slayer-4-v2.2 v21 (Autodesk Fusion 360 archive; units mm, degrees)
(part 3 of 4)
sketch "cam-mount-standoff" plane through (0, 0, 2) normal (0, 0, 1) x axis (-1, 0, 0)
  line L1 (-27.3161, -18.7368) -> (-34.6566, -7.8543)
  line L2 (-7.8768, -19.0795) -> (-13.4582, -18.707)
  line L3 (13.4582, -18.707) -> (7.8768, -19.0795)
  line L4 (7.8768, 19.0795) -> (13.4582, 18.707)
  line L5 (-13.4582, 18.707) -> (-7.8768, 19.0795)
  line L6 (-34.6566, 7.8543) -> (-27.3161, 18.7368)
  line L7 (-34.9985, -6.7359) -> (-34.9985, 6.7359)
  line L8 (-30.1852, -9.1184) -> (-28.4467, -11.6958)
  line L9 (-25.1483, -6) -> (-28.5272, -6)
  line L10 (-28.5272, 6) -> (-25.1483, 6)
  line L11 (-28.4467, 11.6958) -> (-30.1852, 9.1184)
  line L12 (-29.9985, -3) -> (-23.1491, -3)
  line L13 (-31.9985, 1) -> (-31.9985, -1)
  line L14 (-23.1491, 3) -> (-29.9985, 3)
  line L15 (15.3479, -5.782) -> (13.4133, -8.1699)
  line L16 (19.6919, -8.9044) -> (18.7852, -6.3678)
  line L17 (13.4936, -15.6979) -> (15.3167, -15.5763)
  line L18 (13.4133, 8.1699) -> (15.3479, 5.782)
  line L19 (15.3167, 15.5763) -> (13.4936, 15.6979)
  line L20 (18.7852, 6.3678) -> (19.6919, 8.9044)
  line L21 (-15.3479, 5.782) -> (-13.4133, 8.1699)
  line L22 (-19.6919, 8.9044) -> (-18.7852, 6.3678)
  line L23 (-13.4936, 15.6979) -> (-15.3167, 15.5763)
  line L24 (-13.4133, -8.1699) -> (-15.3479, -5.782)
  line L25 (-15.3167, -15.5763) -> (-13.4936, -15.6979)
  line L26 (-18.7852, -6.3678) -> (-19.6919, -8.9044)
  line L27 (18.0216, 10.02) -> (29.5161, 10.02)
  line L28 (22.8958, 10.02) -> (20.2338, 13.9469)
  line L29 (36.0628, 10.02) -> (27.3627, 19.565)
  line L30 (40.7792, 10.02) -> (29.5161, 10.02)
  line L31 (28.5286, 16.0592) -> (34.0332, 10.02)
  line L32 (23.37, 11.9938) -> (24.708, 10.02)
  line L33 (29.4521, 15.7011) -> (38.3863, 7.4856)
  arc A1 centre (-32.9985, -6.7359) radius 2 clockwise from (-34.6566, -7.8543) to (-34.9985, -6.7359)
  arc A2 centre (-24, -16.5) radius 4 clockwise from (-22.465, -20.1938) to (-27.3161, -18.7368)
  arc A3 centre (-14.7902, -38.6626) radius 20 clockwise from (-22.465, -20.1938) to (-13.4582, -18.707)
  arc A4 centre (-9.0756, -37.0396) radius 18 clockwise from (-7.8768, -19.0795) to (-1.2965, -20.8073)
  arc A5 centre (0, -18.1019) radius 3 clockwise from (1.2965, -20.8073) to (-1.2965, -20.8073)
  arc A6 centre (9.0756, -37.0396) radius 18 clockwise from (1.2965, -20.8073) to (7.8768, -19.0795)
  arc A7 centre (14.7902, -38.6626) radius 20 clockwise from (13.4582, -18.707) to (22.465, -20.1938)
  arc A8 centre (24, -16.5) radius 4 clockwise from (26.8498, -13.6931) to (22.465, -20.1938)
  arc A9 centre (41.099, 0.3411) radius 20 clockwise from (26.8498, -13.6931) to (21.1019, 0)
  arc A10 centre (41.099, -0.3411) radius 20 clockwise from (21.1019, 0) to (26.8498, 13.6931)
  arc A11 centre (24, 16.5) radius 4 clockwise from (22.465, 20.1938) to (26.8498, 13.6931)
  arc A12 centre (14.7902, 38.6626) radius 20 clockwise from (22.465, 20.1938) to (13.4582, 18.707)
  arc A13 centre (9.0756, 37.0396) radius 18 clockwise from (7.8768, 19.0795) to (1.2965, 20.8073)
  arc A14 centre (0, 18.1019) radius 3 clockwise from (-1.2965, 20.8073) to (1.2965, 20.8073)
  arc A15 centre (-9.0756, 37.0396) radius 18 clockwise from (-1.2965, 20.8073) to (-7.8768, 19.0795)
  arc A16 centre (-14.7902, 38.6626) radius 20 clockwise from (-13.4582, 18.707) to (-22.465, 20.1938)
  arc A17 centre (-24, 16.5) radius 4 clockwise from (-27.3161, 18.7368) to (-22.465, 20.1938)
  arc A18 centre (-32.9985, 6.7359) radius 2 clockwise from (-34.9985, 6.7359) to (-34.6566, 7.8543)
  arc A19 centre (-28.5272, -8) radius 2 clockwise from (-30.1852, -9.1184) to (-28.5272, -6)
  arc A20 centre (-25.1483, -8) radius 2 clockwise from (-25.1483, -6) to (-23.376, -8.9268)
  arc A21 centre (-41.099, 0.3411) radius 20 clockwise from (-23.376, -8.9268) to (-25.1986, -11.7906)
  arc A22 centre (-26.7887, -10.5774) radius 2 clockwise from (-25.1986, -11.7906) to (-28.4467, -11.6958)
  arc A23 centre (-28.5272, 8) radius 2 clockwise from (-28.5272, 6) to (-30.1852, 9.1184)
  arc A24 centre (-26.7887, 10.5774) radius 2 clockwise from (-28.4467, 11.6958) to (-25.1986, 11.7906)
  arc A25 centre (-41.099, -0.3411) radius 20 clockwise from (-25.1986, 11.7906) to (-23.376, 8.9268)
  arc A26 centre (-25.1483, 8) radius 2 clockwise from (-23.376, 8.9268) to (-25.1483, 6)
  arc A27 centre (-41.099, -0.3411) radius 20 clockwise from (-21.1546, 1.149) to (-21.1019, 0)
  arc A28 centre (-41.099, 0.3411) radius 20 clockwise from (-21.1019, 0) to (-21.1546, -1.149)
  arc A29 centre (-23.1491, -1) radius 2 clockwise from (-21.1546, -1.149) to (-23.1491, -3)
  arc A30 centre (-29.9985, -1) radius 2 clockwise from (-29.9985, -3) to (-31.9985, -1)
  arc A31 centre (-29.9985, 1) radius 2 clockwise from (-31.9985, 1) to (-29.9985, 3)
  arc A32 centre (-23.1491, 1) radius 2 clockwise from (-23.1491, 3) to (-21.1546, 1.149)
  circle C1 centre (18.1019, 0) radius 1.05
  circle C2 centre (24, -16.5) radius 1.55
  arc A33 centre (16.9019, -7.041) radius 2 clockwise from (15.3479, -5.782) to (18.7852, -6.3678)
  arc A34 centre (14.9837, -10.5874) radius 5 clockwise from (19.6919, -8.9044) to (15.3167, -15.5763)
  arc A35 centre (13.3604, -13.7024) radius 2 clockwise from (13.4936, -15.6979) to (12.0163, -12.2214)
  arc A36 centre (10, -10) radius 3 clockwise from (12.9804, -9.6573) to (12.0163, -12.2214)
  arc A37 centre (14.9673, -9.4289) radius 2 clockwise from (12.9804, -9.6573) to (13.4133, -8.1699)
  circle C3 centre (10, -10) radius 1.05
  circle C4 centre (10, 10) radius 1.05
  arc A38 centre (14.9673, 9.4289) radius 2 clockwise from (13.4133, 8.1699) to (12.9804, 9.6573)
  arc A39 centre (10, 10) radius 3 clockwise from (12.0163, 12.2214) to (12.9804, 9.6573)
  arc A40 centre (13.3604, 13.7024) radius 2 clockwise from (12.0163, 12.2214) to (13.4936, 15.6979)
  arc A41 centre (14.9837, 10.5874) radius 5 clockwise from (15.3167, 15.5763) to (19.6919, 8.9044)
  arc A42 centre (16.9019, 7.041) radius 2 clockwise from (18.7852, 6.3678) to (15.3479, 5.782)
  circle C5 centre (24, 16.5) radius 1.55
  circle C6 centre (-24, 16.5) radius 1.55
  arc A43 centre (-16.9019, 7.041) radius 2 clockwise from (-15.3479, 5.782) to (-18.7852, 6.3678)
  arc A44 centre (-14.9837, 10.5874) radius 5 clockwise from (-19.6919, 8.9044) to (-15.3167, 15.5763)
  arc A45 centre (-13.3604, 13.7024) radius 2 clockwise from (-13.4936, 15.6979) to (-12.0163, 12.2214)
  arc A46 centre (-10, 10) radius 3 clockwise from (-12.9804, 9.6573) to (-12.0163, 12.2214)
  arc A47 centre (-14.9673, 9.4289) radius 2 clockwise from (-12.9804, 9.6573) to (-13.4133, 8.1699)
  circle C7 centre (-10, 10) radius 1.05
  circle C8 centre (-10, -10) radius 1.05
  arc A48 centre (-14.9673, -9.4289) radius 2 clockwise from (-13.4133, -8.1699) to (-12.9804, -9.6573)
  arc A49 centre (-10, -10) radius 3 clockwise from (-12.0163, -12.2214) to (-12.9804, -9.6573)
  arc A50 centre (-13.3604, -13.7024) radius 2 clockwise from (-12.0163, -12.2214) to (-13.4936, -15.6979)
  arc A51 centre (-14.9837, -10.5874) radius 5 clockwise from (-15.3167, -15.5763) to (-19.6919, -8.9044)
  arc A52 centre (-16.9019, -7.041) radius 2 clockwise from (-18.7852, -6.3678) to (-15.3479, -5.782)
  circle C9 centre (-24, -16.5) radius 1.55
  circle C10 centre (-18.1019, 0) radius 1.05
  circle C11 centre (0, -18.1019) radius 1.05
  circle C12 centre (0, 18.1019) radius 1.05
  arc A53 centre (0, 3.3668) radius 9 clockwise from (-7.5, 8.3417) to (7.5, 8.3417)
  arc A54 centre (10, 10) radius 3 clockwise from (8.3417, 7.5) to (7.5, 8.3417)
  arc A55 centre (3.3668, 0) radius 9 clockwise from (8.3417, 7.5) to (8.3417, -7.5)
  arc A56 centre (10, -10) radius 3 clockwise from (7.5, -8.3417) to (8.3417, -7.5)
  arc A57 centre (0, -3.3668) radius 9 clockwise from (7.5, -8.3417) to (-7.5, -8.3417)
  arc A58 centre (-10, -10) radius 3 clockwise from (-8.3417, -7.5) to (-7.5, -8.3417)
  arc A59 centre (-3.3668, 0) radius 9 clockwise from (-8.3417, -7.5) to (-8.3417, 7.5)
  arc A60 centre (-10, 10) radius 3 clockwise from (-7.5, 8.3417) to (-8.3417, 7.5)
  circle C13 centre (24, 16.5) radius 3.05
  circle C14 centre (24, 16.5) radius 4.55
  point P148 (22.8958, 10.02)
  point P145 (29.5161, 10.02)
  point P151 (29.5161, 10.02)
  point P150 (36.0628, 10.02)
  point P153 (34.0332, 10.02)
  point P155 (24.708, 10.02)
  point P147 (20.2338, 13.9469)
  point P156 (23.37, 11.9938)
  point P149 (27.3627, 19.565)
  point P154 (28.5286, 16.0592)
  concentric A11 C13
  coincident L27 P148
  coincident P145 P151
  parallel L27 L30
  coincident P150 L30
  coincident L30 P153
  parallel L29 L31
  parallel L28 L32
  coincident L27 P155
  concentric A11 C14
  coincident P147 C14
  tangent L28 C14
  coincident P156 C14
  coincident P149 C14
  tangent L29 C14
  coincident P154 C14
  dimension "d824" diameter C13 = 6.1 (= "( 3.05 * 2 ) * 1 mm")
  dimension "d833" distance L29 L31 = 1.5
  dimension "d834" distance L28 L32 = 1.5
  dimension "d836" distance C13 C14 = 1.5
sketch "cam-mount-skirt" plane through (0, 0, -5) normal (0, 0, 1) x axis (-1, 0, 0)
  line L1 (29.4521, 15.7011) -> (38.3863, 7.4856)
  line L2 (10.5232, 16.1251) -> (13.4179, 16.642)
  line L3 (-9.4685, 16.0316) -> (9.4685, 16.0316)
  line L4 (-13.4179, 16.642) -> (-10.5232, 16.1251)
  line L5 (-25.5, -4.935) -> (-25.5, 4.935)
  line L6 (-10.5232, -16.1251) -> (-13.4179, -16.642)
  line L7 (9.4685, -16.0316) -> (-9.4685, -16.0316)
  line L8 (13.4179, -16.642) -> (10.5232, -16.1251)
  line L9 (38.3863, -7.4856) -> (29.4521, -15.7011)
  line L10 (40.0019, 3.8052) -> (40.0019, -3.8052)
  line L11 (30.4401, -6) -> (27.7146, -6)
  line L12 (29.4762, -11.6034) -> (31.7938, -9.4722)
  line L13 (25.5, 1) -> (25.5, -1)
  line L14 (35.0019, 3) -> (27.5, 3)
  line L15 (37.0019, -1) -> (37.0019, 1)
  line L16 (27.5, -3) -> (35.0019, -3)
  line L17 (-1.1087, 6.926) -> (-3.1817, 10.8944)
  line L18 (-8.4244, 4) -> (-2.8814, 4)
  curve K1 (-10.6866, 5.436) -> (-8.4244, 4)
  curve K2 (-10.6866, 5.436) -> (-12.1729, 8.1647)
  curve K3 (-10, 11.9684) -> (-12.1729, 8.1647)
  line L19 (-4.9544, 11.9684) -> (-10, 11.9684)
  line L20 (10, 11.9684) -> (2.9431, 11.9684)
  curve K4 (10, 11.9684) -> (12.1729, 8.1647)
  curve K5 (10.6866, 5.436) -> (12.1729, 8.1647)
  curve K6 (10.6866, 5.436) -> (8.4244, 4)
  line L21 (5.0161, 4) -> (8.4244, 4)
  line L22 (1.1704, 9.0423) -> (3.2434, 5.074)
  line L23 (2.9431, -11.9684) -> (10, -11.9684)
  line L24 (3.2434, -5.074) -> (1.1704, -9.0423)
  line L25 (8.4244, -4) -> (5.0161, -4)
  curve K7 (10.6866, -5.436) -> (8.4244, -4)
  curve K8 (10.6866, -5.436) -> (12.1729, -8.1647)
  curve K9 (10, -11.9684) -> (12.1729, -8.1647)
  line L26 (-3.1817, -10.8944) -> (-1.1087, -6.926)
  line L27 (-10, -11.9684) -> (-4.9544, -11.9684)
  curve K10 (-10, -11.9684) -> (-12.1729, -8.1647)
  curve K11 (-10.6866, -5.436) -> (-12.1729, -8.1647)
  curve K12 (-10.6866, -5.436) -> (-8.4244, -4)
  line L28 (-2.8814, -4) -> (-8.4244, -4)
  curve K13 (15, 0) -> (18.1183, 6.0086)
  curve K14 (18.1183, 6.0086) -> (22.5, 4.3626)
  line L29 (22.5, -4.3626) -> (22.5, 4.3626)
  curve K15 (18.1183, -6.0086) -> (22.5, -4.3626)
  curve K16 (15, 0) -> (18.1183, -6.0086)
  line L30 (-22.5, 4.3626) -> (-22.5, -4.3626)
  curve K17 (-18.1183, 6.0086) -> (-22.5, 4.3626)
  curve K18 (-15, 0) -> (-18.1183, 6.0086)
  curve K19 (-15, 0) -> (-18.1183, -6.0086)
  curve K20 (-18.1183, -6.0086) -> (-22.5, -4.3626)
  line L31 (27.7146, 6) -> (30.4401, 6)
  line L32 (31.7938, 9.4722) -> (29.4762, 11.6034)
  line L33 (35.8754, 11.8323) -> (41.5019, 6.6585)
  line L34 (41.5019, 6.6585) -> (41.5019, 0)
  line L35 (34.8601, 10.7281) -> (35.8754, 11.8323)
  line L36 (40.0019, 0) -> (41.5019, 0)
  arc A1 centre (35.0019, 3.8052) radius 5 clockwise from (38.3863, 7.4856) to (40.0019, 3.8052)
  arc A2 centre (34.8671, 21.5899) radius 8 clockwise from (29.4521, 15.7011) to (27.6224, 18.1966)
  arc A3 centre (24, 16.5) radius 4 clockwise from (21.8856, 19.8955) to (27.6224, 18.1966)
  arc A4 centre (9.199, 40.2682) radius 24 clockwise from (21.8856, 19.8955) to (13.4179, 16.642)
  arc A5 centre (9.4685, 22.0316) radius 6 clockwise from (10.5232, 16.1251) to (9.4685, 16.0316)
  arc A6 centre (-9.4685, 22.0316) radius 6 clockwise from (-9.4685, 16.0316) to (-10.5232, 16.1251)
  arc A7 centre (-9.199, 40.2682) radius 24 clockwise from (-13.4179, 16.642) to (-21.8856, 19.8955)
  arc A8 centre (-24, 16.5) radius 4 clockwise from (-27.6429, 14.8479) to (-21.8856, 19.8955)
  arc A9 centre (-49.5, 4.935) radius 24 clockwise from (-27.6429, 14.8479) to (-25.5, 4.935)
  arc A10 centre (-49.5, -4.935) radius 24 clockwise from (-25.5, -4.935) to (-27.6429, -14.8479)
  arc A11 centre (-24, -16.5) radius 4 clockwise from (-21.8856, -19.8955) to (-27.6429, -14.8479)
  arc A12 centre (-9.199, -40.2682) radius 24 clockwise from (-21.8856, -19.8955) to (-13.4179, -16.642)
  arc A13 centre (-9.4685, -22.0316) radius 6 clockwise from (-10.5232, -16.1251) to (-9.4685, -16.0316)
  arc A14 centre (9.4685, -22.0316) radius 6 clockwise from (9.4685, -16.0316) to (10.5232, -16.1251)
  arc A15 centre (9.199, -40.2682) radius 24 clockwise from (13.4179, -16.642) to (21.8856, -19.8955)
  arc A16 centre (24, -16.5) radius 4 clockwise from (27.6224, -18.1966) to (21.8856, -19.8955)
  arc A17 centre (34.8671, -21.5899) radius 8 clockwise from (27.6224, -18.1966) to (29.4521, -15.7011)
  arc A18 centre (35.0019, -3.8052) radius 5 clockwise from (40.0019, -3.8052) to (38.3863, -7.4856)
  arc A19 centre (49.5, -4.935) radius 24 clockwise from (26.179, -10.6035) to (25.7341, -8.2786)
  arc A20 centre (27.7146, -8) radius 2 clockwise from (25.7341, -8.2786) to (27.7146, -6)
  arc A21 centre (30.4401, -8) radius 2 clockwise from (30.4401, -6) to (31.7938, -9.4722)
  arc A22 centre (28.1225, -10.1312) radius 2 clockwise from (29.4762, -11.6034) to (26.179, -10.6035)
  arc A23 centre (27.5, 1) radius 2 clockwise from (25.5, 1) to (27.5, 3)
  arc A24 centre (35.0019, 1) radius 2 clockwise from (35.0019, 3) to (37.0019, 1)
  arc A25 centre (35.0019, -1) radius 2 clockwise from (37.0019, -1) to (35.0019, -3)
  arc A26 centre (27.5, -1) radius 2 clockwise from (27.5, -3) to (25.5, -1)
  circle C1 centre (24, 16.5) radius 1.55
  circle C2 centre (-24, 16.5) radius 1.55
  arc A27 centre (-2.8814, 6) radius 2 clockwise from (-1.1087, 6.926) to (-2.8814, 4)
  arc A28 centre (-4.9544, 9.9684) radius 2 clockwise from (-4.9544, 11.9684) to (-3.1817, 10.8944)
  arc A29 centre (5.0161, 6) radius 2 clockwise from (5.0161, 4) to (3.2434, 5.074)
  arc A30 centre (2.9431, 9.9684) radius 2 clockwise from (1.1704, 9.0423) to (2.9431, 11.9684)
  arc A31 centre (2.9431, -9.9684) radius 2 clockwise from (2.9431, -11.9684) to (1.1704, -9.0423)
  arc A32 centre (5.0161, -6) radius 2 clockwise from (3.2434, -5.074) to (5.0161, -4)
  arc A33 centre (-4.9544, -9.9684) radius 2 clockwise from (-3.1817, -10.8944) to (-4.9544, -11.9684)
  arc A34 centre (-2.8814, -6) radius 2 clockwise from (-2.8814, -4) to (-1.1087, -6.926)
  circle C3 centre (-24, -16.5) radius 1.55
  circle C4 centre (24, -16.5) radius 1.55
  arc A35 centre (30.4401, 8) radius 2 clockwise from (31.7938, 9.4722) to (30.4401, 6)
  arc A36 centre (27.7146, 8) radius 2 clockwise from (27.7146, 6) to (25.7341, 8.2786)
  arc A37 centre (49.5, 4.935) radius 24 clockwise from (25.7341, 8.2786) to (26.179, 10.6035)
  arc A38 centre (28.1225, 10.1312) radius 2 clockwise from (26.179, 10.6035) to (29.4762, 11.6034)
  point P132 (41.5019, 6.6585)
  point P133 (41.5019, 6.6585)
  point P134 (34.8601, 10.7281)
  point P135 (40.0019, 0)
  coincident P132 P133
  coincident L1 P134
  perpendicular L1 L35
  midpoint L10 P135
  perpendicular L10 L36
  dimension "d828" distance L1 L33 = 1.5
  dimension "d829" distance L10 L34 = 1.5
extrude "Extrude2" new body sketch "cam-mount-standoff" profile of A10 A11 A12 C13 L27 L28 L29 L30 L31 L32 C14 along normal blind 26.3
base_feature "Base Feature1" bodies "top (1)"
move "Move2"
move "Move1"
work_plane "WorkPlane1" AlongDistance 7
work_plane "WorkPlane2" AlongDistance -22.896 (= "-23.00 mm + 0.104 mm")
extrude "Extrude3" add of existing geometry blind 16
split "Split1" bodies "cam-mount-shell (1)"
split "Split2" bodies "cam-mount-shell (2)"
position "Position10"
sketch "Sketch3" plane through (0, 0, 7) normal (0, 0, -1) x axis (1, 0, 0)
  line L1 (-41.2228, 11.52) -> (-22.896, 11.52)
  line L2 (-41.2228, 0) -> (-41.2228, 11.52)
  line L3 (-38.6076, 0) -> (-41.2228, 0)
  line L4 (-38.6076, 10.02) -> (-38.6076, 0)
  line L5 (-22.896, 10.02) -> (-38.6076, 10.02)
  line L6 (-22.896, 11.52) -> (-22.896, 10.02)
  line L7 (-39.7228, 10.02) -> (-38.6076, 10.02)
  line L8 (-39.7228, 0) -> (-39.7228, 10.02)
  point P6 (-38.6076, 10.02)
  point P8 (-38.6076, 10.02)
  point P10 (-39.7228, 0)
  coincident P6 P8
  perpendicular L4 L7
  coincident L3 P10
  perpendicular L3 L8
  dimension "d841" distance L2 L8 = 1.5
extrude "Extrude4" cut sketch "Sketch3" profile of L3 L4 L7 L8 against normal blind 2.5
extrude "Extrude5" add of existing geometry blind 5
chamfer "Chamfer1" distance 2
sketch "Sketch4" plane through (0, 0, 28.3) normal (0, 0, 1) x axis (-1, 0, 0)
  line L1 (34.2399, 12.02) -> (32.2103, 12.02)
  line L2 (27.3627, 19.565) -> (34.2399, 12.02)
  line L3 (22.8958, 10.02) -> (20.2338, 13.9469)
  line L4 (24.708, 10.02) -> (22.8958, 10.02)
  line L5 (23.37, 11.9938) -> (24.708, 10.02)
  line L6 (32.2103, 12.02) -> (28.5286, 16.0592)
  line L7 (21.4754, 14.7886) -> (23.37, 11.9938)
  line L8 (26.2541, 18.5546) -> (28.5286, 16.0592)
  line L9 (20.2338, 13.9469) -> (21.4754, 14.7886)
  arc A1 centre (24, 16.5) radius 4.55 clockwise from (20.2338, 13.9469) to (27.3627, 19.565)
  arc A2 centre (24, 16.5) radius 4.55 clockwise from (28.5286, 16.0592) to (23.37, 11.9938)
  circle C1 centre (24, 16.5) radius 3.05
  point P9 (23.37, 11.9938)
  point P11 (23.37, 11.9938)
  point P12 (21.4754, 14.7886)
  point P10 (28.5286, 16.0592)
  point P13 (28.5286, 16.0592)
  point P14 (26.2541, 18.5546)
  point P5 (20.2338, 13.9469)
  point P15 (20.2338, 13.9469)
  coincident P9 P11
  coincident C1 P12
  tangent C1 L7
  coincident P10 P13
  coincident C1 P14
  tangent C1 L8
  coincident P5 P15
extrude "Extrude6" cut sketch "Sketch4" profile of A2 C1 L7 L8 against normal blind 46
extrude "Extrude7" cut sketch "Sketch4" profile of L3 L4 L5 L7 L9 against normal blind 6
sketch "Sketch5" plane through (0, 0, 2) normal (0, 0, -1) x axis (1, 0, 0)
  line L1 (-22.896, 10.02) -> (-39.7228, 10.02)
  line L2 (-22.896, 11.52) -> (-22.896, 10.02)
  line L3 (-41.2228, 11.52) -> (-22.896, 11.52)
  line L4 (-41.2228, 0) -> (-41.2228, 11.52)
  line L5 (-39.7228, 0) -> (-41.2228, 0)
  line L6 (-39.7228, 10.02) -> (-39.7228, 0)
  line L7 (-34.8601, 10.7281) -> (-35.8754, 11.8323)
  line L8 (-34.209, 10.02) -> (-34.8601, 10.7281)
  line L9 (-36.2248, 12.2122) -> (-35.8754, 11.8323)
  point P9 (-34.8601, 10.7281)
  point P10 (-34.8601, 10.7281)
  point P11 (-34.209, 10.02)
  point P8 (-35.8754, 11.8323)
  point P12 (-35.8754, 11.8323)
  coincident P9 P10
  coincident L1 P11
  parallel L7 L8
  coincident P8 P12
  parallel L7 L9
extrude "Extrude8" cut sketch "Sketch5" profile of L1 L3 L4 L5 L6 L7 L8 L9 against normal blind 5
combine "Combine1" bodies "cam-mount-shell (2)"
loft "Loft1" sketch "cam-mount-skirt"
fillet "Fillet1" radius 3
fillet "Fillet2" radius 2
fillet "Fillet3" radius 1
fillet "Fillet4" radius 2
fillet "Fillet5" radius 2
fillet "Fillet6" radius 1
fillet "Fillet7" radius 2
chamfer "Chamfer2" distance 1
chamfer "Chamfer3" distance 2
chamfer "Chamfer4" distance 1
component_insert "Component Insert2"
sketch "Sketch7" plane through (0, -10.02, 0) normal (0, 1, 0) x axis (-1, 0, 0)
  curve K1 (33.4338, 2) -> (34.0973, 7)
  line L1 (34.0973, 7) -> (34.209, 7)
  line L2 (35.4854, 7) -> (34.209, 7)
  line L3 (39.7228, 7.7809) -> (39.7228, 7)
  line L4 (43.1065, 10.1501) -> (39.7228, 7.7809)
  line L5 (36.0628, 20.2095) -> (43.1065, 10.1501)
  line L6 (34.0332, 23.1081) -> (36.0628, 20.2095)
  line L7 (22.896, 20.4629) -> (31.612, 26.566)
  line L8 (22.896, 22.2941) -> (22.896, 20.4629)
  line L9 (22.9044, 22.3) -> (22.896, 22.2941)
  line L10 (22.8958, 22.3) -> (22.9044, 22.3)
  line L11 (22.8958, 2) -> (22.8958, 22.3)
  line L12 (33.4338, 2) -> (22.8958, 2)
  curve K2 (33.26, 14.3566) -> (32.1953, 15.8771)
  line L13 (39.7228, 7) -> (35.4854, 7)
  line L14 (31.612, 26.566) -> (34.0332, 23.1081)
  arc A1 centre (32.9724, 15.2882) radius 0.975 clockwise from (33.26, 14.3566) to (32.1953, 15.8771)
extrude "Extrude9" cut sketch "Sketch7" profile of K2 A1 against normal blind 10.5
sketch "Sketch8" plane through (0, -11.52, 0) normal (0, -1, 0) x axis (1, 0, 0)
  curve K1 (-35.5375, 7) -> (-34.9976, 2)
  line L1 (-34.6956, 2) -> (-34.9976, 2)
  line L2 (-34.6956, 22.6295) -> (-34.6956, 2)
  curve K2 (-34.6956, 22.6295) -> (-44.2989, 9.154)
  line L3 (-41.2228, 7) -> (-44.2989, 9.154)
  line L4 (-35.5375, 7) -> (-35.5883, 7)
  curve K3 (-32.1953, 15.8771) -> (-33.26, 14.3566)
  line L5 (-36.1672, 7) -> (-41.2228, 7)
  line L6 (-35.5883, 7) -> (-36.1672, 7)
  arc A1 centre (-32.9724, 15.2882) radius 0.975 clockwise from (-32.1953, 15.8771) to (-33.26, 14.3566)
  circle C1 centre (-32.9724, 15.2882) radius 2.65
  concentric A1 C1
  dimension "d874" diameter C1 = 5.3
extrude "Extrude10" cut sketch "Sketch8" profile of L2 A1 K3 C1 along normal blind 8.5
fillet "Fillet8" radius 3
extrude "Extrude11" add of existing geometry blind 2
fillet "Fillet9" radius 5
mirror "Mirror1" mirrorStitchTolerance 0.1
position "Position9"
position "Position8"
position "Position6"
position "Position7"
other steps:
base_feature "Base Feature1" bodies "cam-mount-shell"
base_feature "Base Feature4"
base_feature "Base Feature3"
base_feature "Base Feature2"
joint_origin "JointOrigin4"
create_component "CreateComponent2"
remove_instance "RemoveInstance2"
remove_instance "RemoveInstance3"
remove_instance "RemoveInstance4"
remove_instance "RemoveInstance5"
remove_instance "RemoveInstance6"
remove_instance "RemoveInstance7"
remove_instance "RemoveInstance8"
remove_instance "RemoveInstance9"
remove_instance "RemoveInstance10"
remove_instance "RemoveInstance11"
remove_instance "RemoveInstance12"
remove_instance "RemoveInstance13"
remove_instance "RemoveInstance14"
joint_origin "JointOrigin5"
joint_origin "JointOrigin6"
joint_origin "JointOrigin7"
joint_origin "JointOrigin8"
joint_origin "JointOrigin9"
joint_origin "JointOrigin10"
create_component "CreateComponent3"
remove_instance "RemoveInstance16"
create_component "CreateComponent1"
named bodies: "center-upper", "arm-fl", "arm-rr", "arm-rl", "center-lower", "cam-mount-shell", "canopy", "cam-mount-shell (1)", "canopy (1)", "canopy-v2", "cam-mount-35", "top (1)", "cam-mount-shell (2)", "puzzle", "arm-fr"

design "20x20 Flight Controller"
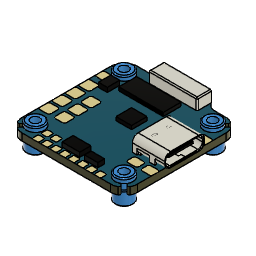
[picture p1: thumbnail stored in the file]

design "Slayer Hurricane 4040"
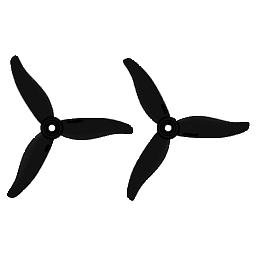
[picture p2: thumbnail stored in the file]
sketch "Sketch1" plane through (0, 0, 0) normal (0, 1, 0) x axis (1, 0, 0)
  curve K1 (5.4694, -4.0404) -> (5.1621, 4.4263)
  curve K2 (23.4739, 6.387) -> (7.3147, 5.303)
  curve K3 (43.581, 4.1632) -> (31.5201, 5.982)
  curve K4 (18.3421, -7.4304) -> (33.5067, -4.4448)
  curve K5 (4.6655, -5.2742) -> (19.2218, -7.6881)
  curve K6 (39.69, -3.7559) -> (54.3074, -3.2468)
  curve K7 (53.947, -7.3026) -> (46.4681, 7.5356)
  curve K8 (51.5, 0) -> (44.2123, 4.0129)
  line L1 (78.7648, 0) -> (0, 0)
  curve K9 (47.845, -5.7624) -> (53.4117, -0.1713)
  curve K10 (8.9395, 5.261) -> (1.3848, 3.5917)
  circle C1 centre (0, 0) radius 6.8
  circle C2 centre (0, 0) radius 2.5
  circle C3 centre (0, 0) radius 50.8
  point P1 (0, 0)
  point P2 (0, 0)
  point P3 (0, 0)
  point P4 (5.1621, 4.4263)
  point P14 (5.4694, -4.0404)
  point P5 (15.3943, 5.845)
  point P6 (37.5505, 5.0726)
  point P12 (25.9244, -5.9376)
  point P13 (11.9437, -6.4811)
  point P10 (46.9987, -3.5013)
  point P8 (50.2076, 0.1165)
  point P7 (47.8561, 2.0065)
  point P29 (0, 0)
  point P9 (50.6284, -2.9668)
  coincident P1 P2
  coincident P1 P3
  coincident C1 P4
  coincident C1 P14
  midpoint P5 K2
  midpoint P6 K3
  midpoint P12 K4
  midpoint P13 K5
  midpoint P10 K6
  midpoint P8 K7
  midpoint P7 K8
  coincident P1 P29
  midpoint P9 K9
  midpoint P4 K10
  concentric C2 C3
  dimension "d1" diameter C1 = 13.6
  dimension "d2" diameter C2 = 5
  dimension "d78" diameter C3 = 101.6 (= "4")
extrude "Extrude1" new body sketch "Sketch1" profile of C1 C2 distance 7
work_plane "WorkPlane6" AlongDistance 4.5
sketch "Sketch3" plane through (4.5, 0, 0) normal (1, 0, 0) x axis (0, 0, -1)
  line L1 (6.8, -3.5) -> (-6.8, -3.5)
  line L2 (-6.8, 3.5) -> (6.8, 3.5)
  line L3 (4, -3.5) -> (4, 3.5)
  line L4 (-3.75, -3.5) -> (-3.75, 3.5)
  curve K1 (-3.75, -3.1239) -> (-3.75, -3.1239)
  curve K2 (-3.5611, -3.317) -> (-3.9389, -2.9308)
  curve K3 (0.2448, -0.7564) -> (-2.2448, -2.2436)
  curve K4 (-3.5886, -0.8664) -> (-0.9748, 1.9804)
  curve K5 (3.4341, 3.3087) -> (4.5659, 2.0069)
  curve K6 (0.0208, 2.5606) -> (2.6178, 3.2817)
  point P7 (4, 3.5)
  point P9 (-3.75, 3.5)
  point P11 (-3.75, -3.1239)
  point P14 (4, 2.6578)
  point P12 (-1, -1.5)
  point P16 (-2.2817, 0.557)
  point P15 (1.3193, 2.9212)
  point P1 (0, 0)
  vertical L3
  coincident L2 P7
  vertical L4
  coincident L2 P9
  coincident L4 P11
  coincident L3 P14
  midpoint P11 K2
  midpoint P12 K3
  midpoint P16 K4
  midpoint P14 K5
  midpoint P15 K6
  dimension "d15" distance P1 L3 = 4
  dimension "d17" distance P1 L4 = 3.75
work_plane "WorkPlane4" AlongDistance 22
sketch "Sketch5" plane through (22, 0, 0) normal (1, 0, 0) x axis (0, 0, -1)
  line L1 (6.0622, 0) -> (-7.0278, 0)
  curve K1 (-4.0404, 0) -> (4.4263, 0)
  line L2 (-7.0278, -3) -> (-7.0278, 0)
  line L3 (6.0622, 3.7) -> (6.0622, 0)
  curve K2 (-7.0278, -3) -> (-7.0278, -3)
  curve K3 (-6.9778, -3.0682) -> (-7.0777, -2.9318)
  point P4 (0, 0)
  point P2 (-7.0278, 0)
  point P7 (-7.0278, -3)
  horizontal L1
  coincident L1 P4
  coincident P2 K1
  perpendicular L1 L2
  midpoint P7 K3
sketch "Sketch8" plane through (22, 0, 0) normal (1, 0, 0) x axis (0, 0, -1)
  curve K1 (-2.9668, 0) -> (-3.75, -3.1239)
  curve K2 (-2.8869, -0.0865) -> (-3.9842, -1.0525)
  curve K3 (0.1695, 0.6998) -> (-6.1031, -0.6998)
  curve K4 (-2.9668, 0) -> (4, 2.6578)
  curve K5 (-7.413, -2.6683) -> (-5.5637, -3.3317)
  curve K6 (5.0928, 3.4589) -> (2.9072, 1.8566)
  point P2 (-3.75, -3.1239)
  point P5 (-3.75, -3.1239)
  point P4 (-2.9668, 0)
  point P7 (-2.9668, 0)
  point P10 (-3.4355, -0.5695)
  point P9 (4, 2.6578)
  point P15 (4, 2.6578)
  point P3 (-6.4884, -3)
  point P8 (6.0622, 3.7)
  point P16 (6.0622, 3.7)
  point P6 (-7.0278, -3)
  point P11 (-7.0278, -3)
  coincident P2 P5
  coincident P4 P7
  midpoint P10 K2
  midpoint P4 K3
  coincident P9 P15
  midpoint P3 K5
  midpoint P15 K6
  coincident P8 P16
  coincident P6 P11
loft "Loft1" sketch "Sketch3" + "Sketch5"
sketch "Sketch20" plane through (0, 0, 0) normal (0, 0, 1) x axis (1, 0, 0)
  curve K1 (50.6284, 0) -> (4.5, 2.6578)
  curve K2 (50.6284, 0) -> (4.5, -3.1239)
  line L1 (4.5, -3.1239) -> (4.5, 2.6578)
  curve K3 (50.6534, 0.1104) -> (4.5, 2.6578)
  curve K4 (22.5489, 5.3352) -> (5.6822, 3.6687)
  curve K5 (5.6102, 3.6045) -> (3.3898, 1.711)
  curve K6 (32.3804, 4.5964) -> (22.8999, 4.8276)
  curve K7 (42.9585, 3.0539) -> (29.1858, 4.862)
  curve K8 (51.8068, -1.7792) -> (49.5, 2)
  line L2 (6.8, -3.5) -> (-6.8, -3.5)
  line L3 (-6.8, 3.5) -> (6.8, 3.5)
  line L4 (6.8, 3.4201) -> (6.8, 3.5)
  line L5 (6.8, -3.5) -> (6.8, -3.2275)
  line L6 (0, 3.5) -> (0, -3.5)
  line L7 (6.8, -3.5) -> (0, -3.5)
  line L8 (0, 3.5) -> (6.8, 3.5)
  point P2 (4.5, 2.6578)
  point P6 (4.5, 2.6578)
  point P4 (4.5, -3.1239)
  point P7 (4.5, -3.1239)
  point P8 (4.5, 2.6578)
  point P12 (50.6534, 0.1104)
  point P9 (14.1155, 4.5019)
  point P10 (27.6402, 4.712)
  point P11 (36.0721, 3.958)
  point P25 (6.8, 3.5)
  point P27 (6.8, 3.5)
  point P28 (6.8, 3.4201)
  point P29 (6.8, -3.2275)
  point P24 (6.8, -3.5)
  point P30 (6.8, -3.5)
  point P1 (0, 0)
  point P31 (0, -3.5)
  point P33 (6.8, 3.5)
  coincident P2 P6
  coincident P4 P7
  coincident P6 P8
  coincident K1 P12
  midpoint P9 K4
  midpoint P8 K5
  midpoint P10 K6
  midpoint P11 K7
  midpoint P12 K8
  coincident P25 P27
  coincident K3 P28
  perpendicular L3 L4
  coincident K2 P29
  coincident P24 P30
  perpendicular L2 L5
  perpendicular L2 L6
  midpoint P1 L6
  midpoint L2 P31
  coincident P25 P33
circular_pattern "C-Pattern1" TotalAngle 360
combine "Combine1"
fillet "Fillet1" radius 0.15 0.2 0.2
chamfer "Chamfer1" distance 1
sketch "Sketch9" plane through (0, 3.5, 0) normal (0, 1, 0) x axis (-1, 0, 0)
  line L1 (2.4871, -1.6776) -> (0, 0)
  line L2 (2.3103, -0.9552) -> (1.7511, -1.7843)
  line L3 (3, 0) -> (0, 0)
  curve K1 (4.241, -5.0571) -> (6.0041, -2.7407)
  curve K2 (2.2591, 6.2013) -> (-0.6285, 6.57)
  curve K3 (-6.5001, -1.1442) -> (-5.3755, -3.8293)
  circle C1 centre (0, 0) radius 2.5
  circle C2 centre (0, 0) radius 4.75
  circle C3 centre (0, 0) radius 2.5
  circle C4 centre (0, 0) radius 3
  arc A1 centre (2.0707, -1.3967) radius 0.5023 clockwise from (2.3103, -0.9552) to (1.7511, -1.7843)
  arc A2 centre (0, 0) radius 6.6 clockwise from (4.241, -5.0571) to (-5.3755, -3.8293)
  arc A3 centre (0, 0) radius 6.6 clockwise from (2.2591, 6.2013) to (6.0041, -2.7407)
  arc A4 centre (0, 0) radius 6.6 clockwise from (-6.5001, -1.1442) to (-0.6285, 6.57)
  point P1 (0, 0)
  point P3 (0, 0)
  point P4 (0, 0)
  point P6 (0, 0)
  point P7 (2.4871, -1.6776)
  point P9 (2.3103, -0.9552)
  point P8 (1.7511, -1.7843)
  point P11 (2.0307, -1.3697)
  point P12 (0, 0)
  point P13 (3, 0)
  coincident P1 P3
  concentric C3 C4
  coincident P4 P6
  coincident C4 P7
  coincident P7 A1
  tangent C4 A1
  coincident C1 P9
  coincident C1 P8
  coincident L1 P11
  perpendicular L1 L2
  midpoint P11 L2
  coincident P1 P12
  coincident C4 P13
  horizontal L3
  dimension "d24" diameter C2 = 9.5
  dimension "d25" diameter C4 = 6
  dimension "d26" distance P8 P9 = 1
  dimension "d35" angle L1 L3 = 34
move "Move1" TranslateX 0 TranslateY -0.025 TranslateZ 0
extrude "Extrude2" add sketch "Sketch9" profile of C1 C2 C3 C4 L1 A1 to an object
chamfer "Chamfer2" distance 0.5
extrude "Extrude3" cut sketch "Sketch9" profile of C1 C3 A1 L2 against normal blind 2
circular_pattern "C-Pattern2" TotalAngle 360
fillet "Fillet2" radius 0.1
fillet "Fillet3" radius 0.1
work_plane "WorkPlane7" AlongDistance 8
sketch "Gemfan Logo" plane through (0, 0, 0) normal (0, 1, 0) x axis (1, 0, 0)
  line L1 (-26.4232, -3.0069) -> (-28.2247, -3.1174)
  curve K1 (-26.4124, -3.6617) -> (-26.4232, -3.0069)
  curve K2 (-25.7177, -4.026) -> (-26.4124, -3.6617)
  curve K3 (-25.0425, -3.8398) -> (-25.7177, -4.026)
  curve K4 (-24.6809, -3.408) -> (-25.0425, -3.8398)
  curve K5 (-24.7437, -2.9905) -> (-24.6809, -3.408)
  curve K6 (-25.5749, -2.6426) -> (-24.7437, -2.9905)
  curve K7 (-27.0668, -1.9141) -> (-25.5749, -2.6426)
  curve K8 (-27.197, -0.7559) -> (-27.0668, -1.9141)
  curve K9 (-26.632, 0.1179) -> (-27.197, -0.7559)
  curve K10 (-25.606, 0.7646) -> (-26.632, 0.1179)
  curve K11 (-24.0506, 0.9999) -> (-25.606, 0.7646)
  curve K12 (-22.4421, 0.5722) -> (-24.0506, 0.9999)
  curve K13 (-22.1863, -0.7886) -> (-22.4421, 0.5722)
  line L2 (-23.9687, -0.8909) -> (-22.1863, -0.7886)
  curve K14 (-24.0611, -0.3016) -> (-23.9687, -0.8909)
  curve K15 (-24.6144, -0.1174) -> (-24.0611, -0.3016)
  curve K16 (-25.1481, -0.2545) -> (-24.6144, -0.1174)
  curve K17 (-25.4252, -0.5881) -> (-25.1481, -0.2545)
  curve K18 (-25.3777, -0.8459) -> (-25.4252, -0.5881)
  curve K19 (-24.8307, -1.0669) -> (-25.3777, -0.8459)
  curve K20 (-23.2694, -1.5969) -> (-24.8307, -1.0669)
  curve K21 (-22.73, -2.262) -> (-23.2694, -1.5969)
  curve K22 (-22.7924, -3.1502) -> (-22.73, -2.262)
  curve K23 (-23.4733, -4.2143) -> (-22.7924, -3.1502)
  curve K24 (-24.6166, -4.953) -> (-23.4733, -4.2143)
  curve K25 (-26.1469, -5.2047) -> (-24.6166, -4.953)
  curve K26 (-28.0667, -4.6154) -> (-26.1469, -5.2047)
  curve K27 (-28.2247, -3.1174) -> (-28.0667, -4.6154)
  line L3 (-18.6296, 0.8976) -> (-20.4837, 0.8976)
  line L4 (-20.1666, -3.6249) -> (-18.6296, 0.8976)
  line L5 (-17.273, -3.6249) -> (-20.1666, -3.6249)
  line L6 (-17.7751, -5.1024) -> (-17.273, -3.6249)
  line L7 (-22.5227, -5.1024) -> (-17.7751, -5.1024)
  line L8 (-20.4837, 0.8976) -> (-22.5227, -5.1024)
  line L9 (-15.0116, -4.112) -> (-12.9067, -4.112)
  line L10 (-15.6406, -5.1024) -> (-15.0116, -4.112)
  line L11 (-17.5337, -5.1024) -> (-15.6406, -5.1024)
  line L12 (-13.2395, 0.8976) -> (-17.5337, -5.1024)
  line L13 (-11.2171, 0.8976) -> (-13.2395, 0.8976)
  line L14 (-11.0016, -5.1024) -> (-11.2171, 0.8976)
  line L15 (-12.9431, -5.1024) -> (-11.0016, -5.1024)
  line L16 (-12.9067, -4.112) -> (-12.9431, -5.1024)
  line L17 (-12.7796, -0.6577) -> (-12.8504, -2.8145)
  line L18 (-14.168, -2.8145) -> (-12.7796, -0.6577)
  line L19 (-12.8504, -2.8145) -> (-14.168, -2.8145)
  line L20 (-7.6316, 0.8976) -> (-9.691, 0.8976)
  line L21 (-7.1107, -1.1265) -> (-7.6316, 0.8976)
  line L22 (-5.2114, 0.8976) -> (-7.1107, -1.1265)
  line L23 (-3.1631, 0.8976) -> (-5.2114, 0.8976)
  line L24 (-6.681, -2.5894) -> (-3.1631, 0.8976)
  line L25 (-7.535, -5.1024) -> (-6.681, -2.5894)
  line L26 (-9.3931, -5.1024) -> (-7.535, -5.1024)
  line L27 (-8.5391, -2.5894) -> (-9.3931, -5.1024)
  line L28 (-9.691, 0.8976) -> (-8.5391, -2.5894)
  line L29 (2.399, 0.8976) -> (-2.5696, 0.8976)
  line L30 (1.9637, -0.3834) -> (2.399, 0.8976)
  line L31 (-1.1469, -0.3834) -> (1.9637, -0.3834)
  line L32 (-1.4709, -1.3371) -> (-1.1469, -0.3834)
  line L33 (1.4145, -1.3371) -> (-1.4709, -1.3371)
  line L34 (0.9986, -2.5608) -> (1.4145, -1.3371)
  line L35 (-1.8868, -2.5608) -> (0.9986, -2.5608)
  line L36 (-2.2888, -3.7436) -> (-1.8868, -2.5608)
  line L37 (0.9117, -3.7436) -> (-2.2888, -3.7436)
  line L38 (0.45, -5.1024) -> (0.9117, -3.7436)
  line L39 (-4.6087, -5.1024) -> (0.45, -5.1024)
  line L40 (-2.5696, 0.8976) -> (-4.6087, -5.1024)
  line L41 (3.5123, 0.8976) -> (1.4732, -5.1024)
  line L42 (6.6023, 0.8976) -> (3.5123, 0.8976)
  curve K28 (7.866, 0.7503) -> (6.6023, 0.8976)
  curve K29 (8.4129, 0.2039) -> (7.866, 0.7503)
  curve K30 (8.3608, -0.7682) -> (8.4129, 0.2039)
  curve K31 (7.8551, -1.6297) -> (8.3608, -0.7682)
  curve K32 (7.07, -2.217) -> (7.8551, -1.6297)
  curve K33 (6.3381, -2.4544) -> (7.07, -2.217)
  curve K34 (6.7456, -2.6756) -> (6.3381, -2.4544)
  curve K35 (6.9349, -2.991) -> (6.7456, -2.6756)
  curve K36 (7.0679, -3.3638) -> (6.9349, -2.991)
  line L43 (7.3749, -5.1024) -> (7.0679, -3.3638)
  line L44 (5.28, -5.1024) -> (7.3749, -5.1024)
  line L45 (4.9121, -3.2688) -> (5.28, -5.1024)
  curve K37 (4.7337, -2.8064) -> (4.9121, -3.2688)
  curve K38 (4.3267, -2.6672) -> (4.7337, -2.8064)
  line L46 (4.1629, -2.6672) -> (4.3267, -2.6672)
  line L47 (3.3354, -5.1024) -> (4.1629, -2.6672)
  line L48 (1.4732, -5.1024) -> (3.3354, -5.1024)
  line L49 (5.33, -1.5335) -> (4.5482, -1.5335)
  curve K39 (5.8489, -1.4517) -> (5.33, -1.5335)
  curve K40 (6.2137, -1.2634) -> (5.8489, -1.4517)
  curve K41 (6.4486, -0.9155) -> (6.2137, -1.2634)
  curve K42 (6.416, -0.4694) -> (6.4486, -0.9155)
  curve K43 (5.7772, -0.3139) -> (6.416, -0.4694)
  line L50 (4.9628, -0.3139) -> (5.7772, -0.3139)
  line L51 (4.5482, -1.5335) -> (4.9628, -0.3139)
  line L52 (14.5996, 0.8976) -> (10.0157, 0.8976)
  line L53 (14.1614, -0.3916) -> (14.5996, 0.8976)
  line L54 (11.4397, -0.3916) -> (14.1614, -0.3916)
  line L55 (11.0836, -1.4394) -> (11.4397, -0.3916)
  line L56 (13.4083, -1.4394) -> (11.0836, -1.4394)
  line L57 (12.9966, -2.6508) -> (13.4083, -1.4394)
  line L58 (10.6719, -2.6508) -> (12.9966, -2.6508)
  line L59 (9.8388, -5.1024) -> (10.6719, -2.6508)
  line L60 (7.9766, -5.1024) -> (9.8388, -5.1024)
  line L61 (10.0157, 0.8976) -> (7.9766, -5.1024)
  line L62 (14.6897, -4.112) -> (16.7946, -4.112)
  line L63 (14.0606, -5.1024) -> (14.6897, -4.112)
  line L64 (12.1676, -5.1024) -> (14.0606, -5.1024)
  line L65 (16.4618, 0.8976) -> (12.1676, -5.1024)
  line L66 (18.4841, 0.8976) -> (16.4618, 0.8976)
  line L67 (18.6996, -5.1024) -> (18.4841, 0.8976)
  line L68 (16.7581, -5.1024) -> (18.6996, -5.1024)
  line L69 (16.7946, -4.112) -> (16.7581, -5.1024)
  line L70 (16.9216, -0.6577) -> (16.8508, -2.8145)
  line L71 (15.5332, -2.8145) -> (16.9216, -0.6577)
  line L72 (16.8508, -2.8145) -> (15.5332, -2.8145)
  line L73 (23.0716, 0.8976) -> (21.3404, 0.8976)
  line L74 (24.2027, -2.4219) -> (23.0716, 0.8976)
  line L75 (25.3308, 0.8976) -> (24.2027, -2.4219)
  line L76 (27.0784, 0.8976) -> (25.3308, 0.8976)
  line L77 (25.0393, -5.1024) -> (27.0784, 0.8976)
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work_plane "WorkPlane8" AlongDistance 10
mirror "Mirror2" mirrorStitchTolerance 0
sketch "GEMFAN" plane through (28.9566, 10, -18.6867) normal (0, 1, 0) x axis (1, 0, 0)
  line L1 (-18.7002, -15.1005) -> (-18.9977, -15.145)
  curve K1 (-18.6889, -15.209) -> (-18.7002, -15.1005)
  curve K2 (-18.5682, -15.2594) -> (-18.6889, -15.209)
  curve K3 (-18.4588, -15.2187) -> (-18.5682, -15.2594)
  curve K4 (-18.4051, -15.1417) -> (-18.4588, -15.2187)
  curve K5 (-18.4216, -15.0733) -> (-18.4051, -15.1417)
  curve K6 (-18.5646, -15.0277) -> (-18.4216, -15.0733)
  curve K7 (-18.8229, -14.9284) -> (-18.5646, -15.0277)
  curve K8 (-18.8613, -14.738) -> (-18.8229, -14.9284)
  curve K9 (-18.7802, -14.5847) -> (-18.8613, -14.738)
  curve K10 (-18.6193, -14.4624) -> (-18.7802, -14.5847)
  curve K11 (-18.3644, -14.4007) -> (-18.6193, -14.4624)
  curve K12 (-18.0912, -14.4484) -> (-18.3644, -14.4007)
  curve K13 (-18.0289, -14.6706) -> (-18.0912, -14.4484)
  line L2 (-18.3234, -14.7135) -> (-18.0289, -14.6706)
  curve K14 (-18.3473, -14.617) -> (-18.3234, -14.7135)
  curve K15 (-18.4418, -14.5944) -> (-18.3473, -14.617)
  curve K16 (-18.5284, -14.625) -> (-18.4418, -14.5944)
  curve K17 (-18.5696, -14.6844) -> (-18.5284, -14.625)
  curve K18 (-18.558, -14.7265) -> (-18.5696, -14.6844)
  curve K19 (-18.4639, -14.7552) -> (-18.558, -14.7265)
  curve K20 (-18.197, -14.8206) -> (-18.4639, -14.7552)
  curve K21 (-18.0978, -14.9231) -> (-18.197, -14.8206)
  curve K22 (-18.0953, -15.0715) -> (-18.0978, -14.9231)
  curve K23 (-18.1929, -15.2581) -> (-18.0953, -15.0715)
  curve K24 (-18.3719, -15.3973) -> (-18.1929, -15.2581)
  curve K25 (-18.6224, -15.4614) -> (-18.3719, -15.3973)
  curve K26 (-18.9497, -15.3914) -> (-18.6224, -15.4614)
  curve K27 (-18.9977, -15.145) -> (-18.9497, -15.3914)
  line L3 (-17.4629, -14.339) -> (-17.7707, -14.3659)
  line L4 (-17.6524, -15.1122) -> (-17.4629, -14.339)
  line L5 (-17.172, -15.0702) -> (-17.6524, -15.1122)
  line L6 (-17.2339, -15.3228) -> (-17.172, -15.0702)
  line L7 (-18.0221, -15.3917) -> (-17.2339, -15.3228)
  line L8 (-17.7707, -14.3659) -> (-18.0221, -15.3917)
  line L9 (-16.7894, -15.1182) -> (-16.4399, -15.0876)
  line L10 (-16.8795, -15.2918) -> (-16.7894, -15.1182)
  line L11 (-17.1938, -15.3193) -> (-16.8795, -15.2918)
  line L12 (-16.568, -14.2607) -> (-17.1938, -15.3193)
  line L13 (-16.2322, -14.2313) -> (-16.568, -14.2607)
  line L14 (-16.1092, -15.2244) -> (-16.2322, -14.2313)
  line L15 (-16.4316, -15.2526) -> (-16.1092, -15.2244)
  line L16 (-16.4399, -15.0876) -> (-16.4316, -15.2526)
  line L17 (-16.469, -14.5122) -> (-16.4494, -14.8714)
  line L18 (-16.6682, -14.8905) -> (-16.469, -14.5122)
  line L19 (-16.4494, -14.8714) -> (-16.6682, -14.8905)
  line L20 (-15.6369, -14.1792) -> (-15.9788, -14.2091)
  line L21 (-15.521, -14.5077) -> (-15.6369, -14.1792)
  line L22 (-15.235, -14.1441) -> (-15.521, -14.5077)
  line L23 (-14.895, -14.1143) -> (-15.235, -14.1441)
  line L24 (-15.4284, -14.7444) -> (-14.895, -14.1143)
  line L25 (-15.5337, -15.174) -> (-15.4284, -14.7444)
  line L26 (-15.8422, -15.201) -> (-15.5337, -15.174)
  line L27 (-15.7369, -14.7714) -> (-15.8422, -15.201)
  line L28 (-15.9788, -14.2091) -> (-15.7369, -14.7714)
  line L29 (-13.9715, -14.0335) -> (-14.7964, -14.1057)
  line L30 (-14.0251, -14.2525) -> (-13.9715, -14.0335)
  line L31 (-14.5416, -14.2977) -> (-14.0251, -14.2525)
  line L32 (-14.5815, -14.4608) -> (-14.5416, -14.2977)
  line L33 (-14.1025, -14.4188) -> (-14.5815, -14.4608)
  line L34 (-14.1537, -14.6281) -> (-14.1025, -14.4188)
  line L35 (-14.6328, -14.67) -> (-14.1537, -14.6281)
  line L36 (-14.6824, -14.8722) -> (-14.6328, -14.67)
  line L37 (-14.151, -14.8257) -> (-14.6824, -14.8722)
  line L38 (-14.2079, -15.058) -> (-14.151, -14.8257)
  line L39 (-15.0478, -15.1315) -> (-14.2079, -15.058)
  line L40 (-14.7964, -14.1057) -> (-15.0478, -15.1315)
  line L41 (-13.7866, -14.0173) -> (-14.038, -15.0432)
  line L42 (-13.2736, -13.9725) -> (-13.7866, -14.0173)
  curve K28 (-13.0616, -13.9786) -> (-13.2736, -13.9725)
  curve K29 (-12.9629, -14.0613) -> (-13.0616, -13.9786)
  curve K30 (-12.9574, -14.2235) -> (-12.9629, -14.0613)
  curve K31 (-13.0289, -14.3739) -> (-12.9574, -14.2235)
  curve K32 (-13.1507, -14.4828) -> (-13.0289, -14.3739)
  curve K33 (-13.2688, -14.5328) -> (-13.1507, -14.4828)
  curve K34 (-13.1979, -14.5636) -> (-13.2688, -14.5328)
  curve K35 (-13.1619, -14.6133) -> (-13.1979, -14.5636)
  curve K36 (-13.1344, -14.6732) -> (-13.1619, -14.6133)
  line L43 (-13.0581, -14.9574) -> (-13.1344, -14.6732)
  line L44 (-13.406, -14.9879) -> (-13.0581, -14.9574)
  line L45 (-13.4937, -14.6888) -> (-13.406, -14.9879)
  curve K37 (-13.53, -14.6146) -> (-13.4937, -14.6888)
  curve K38 (-13.5996, -14.5974) -> (-13.53, -14.6146)
  line L46 (-13.6268, -14.5998) -> (-13.5996, -14.5974)
  line L47 (-13.7288, -15.0161) -> (-13.6268, -14.5998)
  line L48 (-14.038, -15.0432) -> (-13.7288, -15.0161)
  line L49 (-13.4495, -14.3946) -> (-13.5793, -14.4059)
  curve K39 (-13.3645, -14.3735) -> (-13.4495, -14.3946)
  curve K40 (-13.3067, -14.3369) -> (-13.3645, -14.3735)
  curve K41 (-13.2728, -14.2757) -> (-13.3067, -14.3369)
  curve K42 (-13.2847, -14.2021) -> (-13.2728, -14.2757)
  curve K43 (-13.393, -14.1856) -> (-13.2847, -14.2021)
  line L50 (-13.5282, -14.1974) -> (-13.393, -14.1856)
  line L51 (-13.5793, -14.4059) -> (-13.5282, -14.1974)
  line L52 (-11.9458, -13.8563) -> (-12.7069, -13.9229)
  line L53 (-11.9998, -14.0767) -> (-11.9458, -13.8563)
  line L54 (-12.4517, -14.1162) -> (-11.9998, -14.0767)
  line L55 (-12.4956, -14.2954) -> (-12.4517, -14.1162)
  line L56 (-12.1096, -14.2616) -> (-12.4956, -14.2954)
  line L57 (-12.1604, -14.4687) -> (-12.1096, -14.2616)
  line L58 (-12.5464, -14.5025) -> (-12.1604, -14.4687)
  line L59 (-12.6491, -14.9216) -> (-12.5464, -14.5025)
  line L60 (-12.9583, -14.9487) -> (-12.6491, -14.9216)
  line L61 (-12.7069, -13.9229) -> (-12.9583, -14.9487)
  line L62 (-11.858, -14.6867) -> (-11.5086, -14.6562)
  line L63 (-11.9481, -14.8603) -> (-11.858, -14.6867)
  line L64 (-12.2624, -14.8878) -> (-11.9481, -14.8603)
  line L65 (-11.6366, -13.8292) -> (-12.2624, -14.8878)
  line L66 (-11.3008, -13.7999) -> (-11.6366, -13.8292)
  line L67 (-11.1779, -14.7929) -> (-11.3008, -13.7999)
  line L68 (-11.5002, -14.8211) -> (-11.1779, -14.7929)
  line L69 (-11.5086, -14.6562) -> (-11.5002, -14.8211)
  line L70 (-11.5376, -14.0808) -> (-11.5181, -14.4399)
  line L71 (-11.7368, -14.4591) -> (-11.5376, -14.0808)
  line L72 (-11.5181, -14.4399) -> (-11.7368, -14.4591)
  line L73 (-10.5391, -13.7332) -> (-10.8266, -13.7584)
  line L74 (-10.3031, -14.2679) -> (-10.5391, -13.7332)
  line L75 (-10.164, -13.7004) -> (-10.3031, -14.2679)
  line L76 (-9.8739, -13.675) -> (-10.164, -13.7004)
  line L77 (-10.1253, -14.7008) -> (-9.8739, -13.675)
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extrude "Extrude4" sketch "GEMFAN" blind 0.1 named "d44"
sketch "Sketch13" plane through (0, 10, 0) normal (0, 1, 0) x axis (1, 0, 0)
  line L1 (-2.5624, -10.9882) -> (-2.8879, -10.8364)
  line L2 (-2.2874, -10.3984) -> (-2.5624, -10.9882)
  line L3 (-2.1344, -10.4698) -> (-2.2874, -10.3984)
  line L4 (-1.5427, -11.501) -> (-2.1344, -10.4698)
  line L5 (-1.6063, -11.6373) -> (-1.5427, -11.501)
  line L6 (-2.4872, -11.2265) -> (-1.6063, -11.6373)
  line L7 (-2.5728, -11.4101) -> (-2.4872, -11.2265)
  line L8 (-2.7258, -11.3388) -> (-2.5728, -11.4101)
  line L9 (-2.6402, -11.1551) -> (-2.7258, -11.3388)
  line L10 (-2.9657, -11.0034) -> (-2.6402, -11.1551)
  line L11 (-2.8879, -10.8364) -> (-2.9657, -11.0034)
  line L12 (-1.7964, -11.3454) -> (-2.4094, -11.0596)
  line L13 (-2.2109, -10.6339) -> (-1.7964, -11.3454)
  line L14 (-2.4094, -11.0596) -> (-2.2109, -10.6339)
  curve K1 (-2.0955, -11.9008) -> (-2.4604, -11.6702)
  curve K2 (-1.9375, -12.154) -> (-2.0955, -11.9008)
  curve K3 (-1.9726, -12.4374) -> (-1.9375, -12.154)
  curve K4 (-2.1061, -12.6088) -> (-1.9726, -12.4374)
  curve K5 (-2.2967, -12.6859) -> (-2.1061, -12.6088)
  curve K6 (-2.5383, -12.676) -> (-2.2967, -12.6859)
  curve K7 (-2.8738, -12.5568) -> (-2.5383, -12.676)
  curve K8 (-3.2372, -12.3275) -> (-2.8738, -12.5568)
  curve K9 (-3.3958, -12.0746) -> (-3.2372, -12.3275)
  curve K10 (-3.3608, -11.7901) -> (-3.3958, -12.0746)
  curve K11 (-3.0758, -11.547) -> (-3.3608, -11.7901)
  curve K12 (-2.4604, -11.6702) -> (-3.0758, -11.547)
  curve K13 (-3.0226, -11.7124) -> (-2.5404, -11.8418)
  curve K14 (-3.2235, -11.8541) -> (-3.0226, -11.7124)
  curve K15 (-3.2024, -12.0993) -> (-3.2235, -11.8541)
  curve K16 (-2.7938, -12.3852) -> (-3.2024, -12.0993)
  curve K17 (-2.3113, -12.5148) -> (-2.7938, -12.3852)
  curve K18 (-2.1099, -12.3711) -> (-2.3113, -12.5148)
  curve K19 (-2.1216, -12.1421) -> (-2.1099, -12.3711)
  curve K20 (-2.5404, -11.8418) -> (-2.1216, -12.1421)
  line L15 (-3.5474, -13.1007) -> (-3.8729, -12.9489)
  line L16 (-3.2724, -12.5109) -> (-3.5474, -13.1007)
  line L17 (-3.1194, -12.5822) -> (-3.2724, -12.5109)
  line L18 (-2.5277, -13.6134) -> (-3.1194, -12.5822)
  line L19 (-2.5913, -13.7497) -> (-2.5277, -13.6134)
  line L20 (-3.4723, -13.3389) -> (-2.5913, -13.7497)
  line L21 (-3.5579, -13.5226) -> (-3.4723, -13.3389)
  line L22 (-3.7109, -13.4512) -> (-3.5579, -13.5226)
  line L23 (-3.6253, -13.2676) -> (-3.7109, -13.4512)
  line L24 (-3.9508, -13.1158) -> (-3.6253, -13.2676)
  line L25 (-3.8729, -12.9489) -> (-3.9508, -13.1158)
  line L26 (-2.7815, -13.4579) -> (-3.3944, -13.172)
  line L27 (-3.196, -12.7464) -> (-2.7815, -13.4579)
  line L28 (-3.3944, -13.172) -> (-3.196, -12.7464)
  curve K21 (-3.0805, -14.0133) -> (-3.4455, -13.7827)
  curve K22 (-2.9226, -14.2664) -> (-3.0805, -14.0133)
  curve K23 (-2.9576, -14.5498) -> (-2.9226, -14.2664)
  curve K24 (-3.0912, -14.7213) -> (-2.9576, -14.5498)
  curve K25 (-3.2818, -14.7983) -> (-3.0912, -14.7213)
  curve K26 (-3.5233, -14.7885) -> (-3.2818, -14.7983)
  curve K27 (-3.8589, -14.6692) -> (-3.5233, -14.7885)
  curve K28 (-4.2222, -14.44) -> (-3.8589, -14.6692)
  curve K29 (-4.3809, -14.187) -> (-4.2222, -14.44)
  curve K30 (-4.3458, -13.9025) -> (-4.3809, -14.187)
  curve K31 (-4.0609, -13.6594) -> (-4.3458, -13.9025)
  curve K32 (-3.4455, -13.7827) -> (-4.0609, -13.6594)
  curve K33 (-4.0076, -13.8248) -> (-3.5255, -13.9543)
  curve K34 (-4.2086, -13.9665) -> (-4.0076, -13.8248)
  curve K35 (-4.1875, -14.2117) -> (-4.2086, -13.9665)
  curve K36 (-3.7789, -14.4977) -> (-4.1875, -14.2117)
  curve K37 (-3.2963, -14.6273) -> (-3.7789, -14.4977)
  curve K38 (-3.0949, -14.4836) -> (-3.2963, -14.6273)
  curve K39 (-3.1067, -14.2545) -> (-3.0949, -14.4836)
  curve K40 (-3.5255, -13.9543) -> (-3.1067, -14.2545)
extrude "Extrude6" sketch "Sketch13" blind 0.1 (= "d44")
work_plane "WorkPlane9" AlongDistance -24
